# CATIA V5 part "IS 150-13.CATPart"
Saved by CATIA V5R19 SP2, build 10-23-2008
Part number: IS 150-13
Bounding box of the stored display mesh (mm): x -15.868 to 15.868, y -15.868 to 15.868, z 0 to 75.4
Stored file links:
  C:\Users\Bora\Desktop\3D Katı model\IS serisi\IS 150\IS 150-13.CATPart
  C:\Program Files\Dassault Systemes\B19\intel_a\reffiles\standard\MetricThickPitch.txt
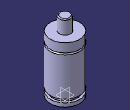
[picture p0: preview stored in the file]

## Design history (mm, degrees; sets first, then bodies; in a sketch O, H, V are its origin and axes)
Body1 (main body)
  Sketch1 on yz-plane, origin (0, 0, 0), H (0, 1, 0), V (0, 0, 1)
    point P3 (6, 74.4)
    point P5 (6, 74.4)
    point P7 (16, 50.9)
    point P8 (16, 48.9)
    point P12 (16, 48.9)
    point P13 (16, 50.9)
    line L1 (16, 0) -> (16, 4)
    line L2 (6, 74.4) -> (6, 60.4)
    arc A1 centre (5, 74.4) radius 1 from (6, 74.4) to (5, 75.4) ccw
    arc A2 centre (16, 49.9) radius 1 from (16, 50.9) to (16, 48.9) ccw
    line L3 (13.5, 7.5) -> (13.5, 4)
    line L4 (16, 7.5) -> (16, 48.9)
    line L5 (16, 50.9) -> (16, 60.4)
    line L6 (5, 75.4) -> (0, 75.4)
    line L7 (6, 60.4) -> (16, 60.4)
    line L8 (13.5, 7.5) -> (16, 7.5)
    line L9 (13.5, 4) -> (16, 4)
    line L10 (16, 0) -> (0, 0)
    tangency: L6 A1
    horizontal: L7 H, L8 H, L9 H, L10 H
    coincidence: P3 P5, P7 P13, P8 P12
  Shaft1: profile Sketch1, axis Sketch1.V, angle 360
  Sketch2 on face of Shaft1 from Sketch1.L10, origin (0, 0, 0), H (1, 0, 0), V (0, -1, 0)
    point P1 (0, 0)
  Hole1: placed by Sketch2, at (0, 0, 0) direction (0, 0, 1), diameter 6.647, depth 7, threaded "M8", thread diameter 8, thread depth 7, pitch 1.25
